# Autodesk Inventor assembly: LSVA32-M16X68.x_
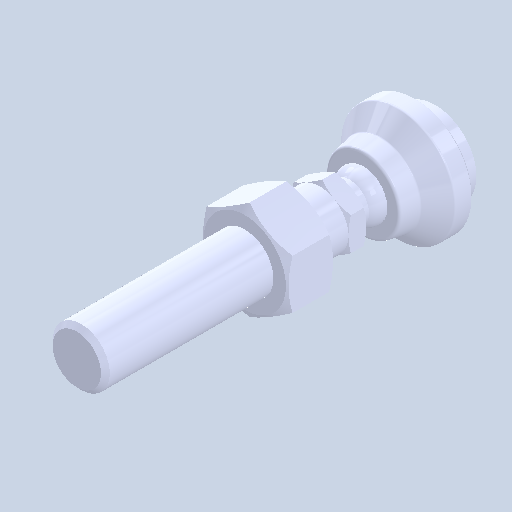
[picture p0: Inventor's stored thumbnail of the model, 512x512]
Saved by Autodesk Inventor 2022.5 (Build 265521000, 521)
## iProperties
Created: 2024-08
Part Number: LSVA32-M16X68.x_
Document SubType Name: Assembly
Designer: ImaoCorp
Author: ImaoCorp
Sending System: SOLIDWORKS 2022-2022290
MC: AMD64
MC_MODEL: Intel64 Family 6 Model 60 Stepping 3, GenuineIntel
OS: Windows_NT
FRU: Parasolid Version 33.1, build 260,  4-25-2022
FORMAT: text
GUISE: transmit
KEY: FILELSVA32-M16X68.x_t
DATE: Fri Aug 23 16:06:58 2024
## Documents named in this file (4)
- X:\14_SW2022-Inv2022\06_2024-10新製品(SME)\ELS_データ\l\lsva32-m16x68\LSVA32-M16X68.x_.iam
- X:\14_SW2022-Inv2022\06_2024-10新製品(SME)\ELS_データ\l\lsva32-m16x68\LSVA32-M16X68_01.ipt
- X:\14_SW2022-Inv2022\06_2024-10新製品(SME)\ELS_データ\l\lsva32-m16x68\LSVA32-M16X68_02.ipt
- X:\14_SW2022-Inv2022\06_2024-10新製品(SME)\ELS_データ\l\lsva32-m16x68\LSVA32-M16X68_03.ipt
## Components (3 placed, 3 different names)
1. LSVA32-M16X68_01
2. LSVA32-M16X68_02
3. LSVA32-M16X68_03
